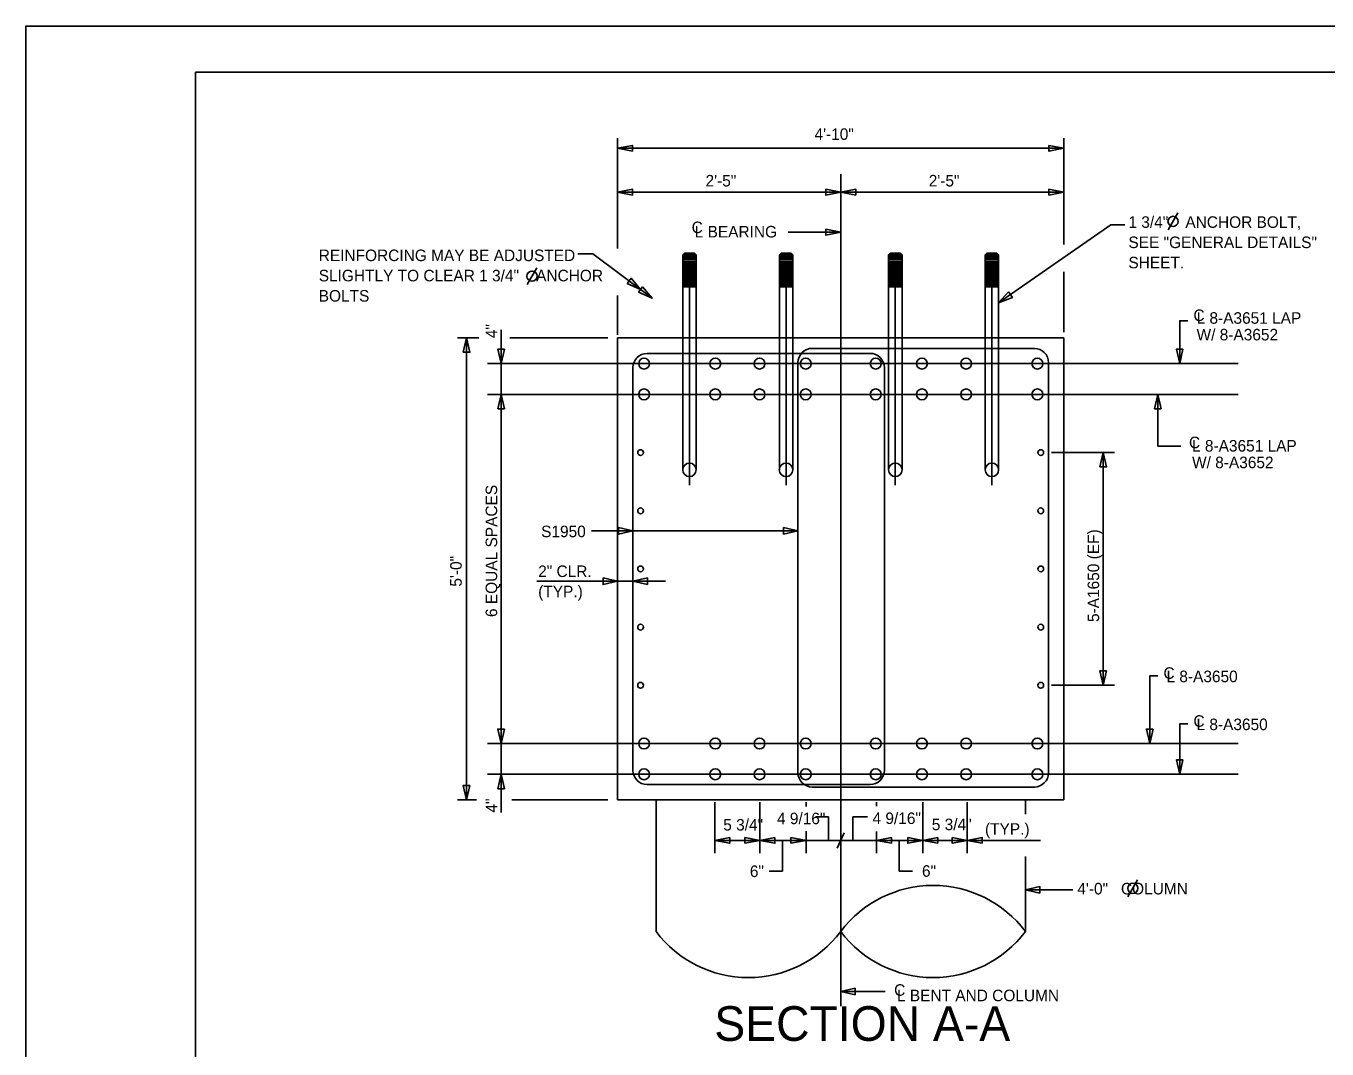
# Model space of a CAD drawing. Extents: x 1970675.2 to 1970711.3, y 796145.2 to 796167.2.
# Drawn here: x 1970675.24 to 1970689.32, y 796156.18 to 796167.25 of the extents above; entities that cross this region are included whole.
import ezdxf

# ---------------------------------------------------------------- set-up
doc = ezdxf.new("R2010")
doc.units = 0
for name, color, linetype in [('BR_AUTO DIMENSION', 7, 'Continuous'), ('BR_BORDER LINES', 7, 'Continuous'), ('BR_CENTER LINES', 7, 'Continuous'), ('BR_CONCRETE', 7, 'Continuous'), ('BR_REBAR', 7, 'Continuous'), ('BR_STRUCTURAL STEEL', 7, 'Continuous'), ('BR_TEXT', 7, 'Continuous'), ('Level 31', 7, 'Continuous')]:
    doc.layers.add(name, color=color, linetype=linetype)

msp = doc.modelspace()

# ---------------------------------------------------------------- linework, layer by layer
at = {"layer": 'BR_AUTO DIMENSION'}
for p, q in [((1970681.641, 796164.84), (1970681.641, 796166.031)), ((1970686.474, 796164.881), (1970686.474, 796166.031)), ((1970681.641, 796165.924), (1970686.474, 796165.924)), ((1970684.058, 796165.275), (1970684.058, 796165.643)), ((1970681.641, 796165.448), (1970684.058, 796165.448)), ((1970686.474, 796165.448), (1970684.058, 796165.448)), ((1970685.768, 796164.249), (1970686.981, 796165.095)), ((1970686.981, 796165.095), (1970687.135, 796165.095)), ((1970683.488, 796165.015), (1970684.058, 796165.015)), ((1970686.474, 796163.933), (1970686.474, 796164.585)), ((1970681.641, 796163.904), (1970681.641, 796164.33)), ((1970680.381, 796163.96), (1970680.381, 796158.734)), ((1970680.138, 796163.871), (1970679.908, 796163.871)), ((1970680.006, 796163.871), (1970680.006, 796158.871)), ((1970681.537, 796163.871), (1970680.475, 796163.871)), ((1970687.491, 796163.26), (1970687.491, 796162.698)), ((1970687.491, 796162.698), (1970687.742, 796162.698)), ((1970687.021, 796162.63), (1970686.339, 796162.63)), ((1970686.898, 796162.63), (1970686.898, 796160.111)), ((1970683.595, 796161.783), (1970681.361, 796161.783)), ((1970682.159, 796161.238), (1970680.767, 796161.238)), ((1970687.021, 796160.111), (1970686.339, 796160.111)), ((1970680.113, 796158.871), (1970679.908, 796158.871)), ((1970681.537, 796158.871), (1970680.496, 796158.871)), ((1970682.694, 796158.295), (1970682.694, 796158.847)), ((1970683.182, 796158.295), (1970683.182, 796158.847)), ((1970683.682, 796158.798), (1970683.682, 796158.847)), ((1970684.446, 796158.803), (1970684.446, 796158.847)), ((1970684.946, 796158.295), (1970684.946, 796158.847)), ((1970685.428, 796158.295), (1970685.428, 796158.847)), ((1970685.428, 796158.295), (1970685.428, 796158.847)), ((1970683.784, 796158.687), (1970683.926, 796158.687)), ((1970683.926, 796158.433), (1970683.926, 796158.687)), ((1970684.19, 796158.687), (1970684.347, 796158.687)), ((1970684.19, 796158.433), (1970684.19, 796158.687)), ((1970685.428, 796158.433), (1970682.694, 796158.433)), ((1970683.426, 796158.433), (1970683.426, 796158.1)), ((1970683.682, 796158.295), (1970683.682, 796158.532)), ((1970684.021, 796158.35), (1970684.095, 796158.515)), ((1970684.446, 796158.295), (1970684.446, 796158.528)), ((1970684.692, 796158.433), (1970684.692, 796158.1)), ((1970686.22, 796158.433), (1970685.428, 796158.433)), ((1970683.426, 796158.1), (1970683.282, 796158.1)), ((1970684.692, 796158.1), (1970684.836, 796158.1)), ((1970686.058, 796157.896), (1970686.57, 796157.896)), ((1970684.058, 796156.797), (1970684.54, 796156.797))]:
    msp.add_line(p, q, dxfattribs=at)
for points in [[(1970681.804, 796165.892), (1970681.641, 796165.924), (1970681.804, 796165.955)], [(1970686.312, 796165.955), (1970686.474, 796165.924), (1970686.312, 796165.892)], [(1970681.804, 796165.417), (1970681.641, 796165.448), (1970681.804, 796165.479)], [(1970683.895, 796165.479), (1970684.058, 796165.448), (1970683.895, 796165.417)], [(1970684.22, 796165.417), (1970684.058, 796165.448), (1970684.22, 796165.479)], [(1970686.312, 796165.479), (1970686.474, 796165.448), (1970686.312, 796165.417)], [(1970683.895, 796165.047), (1970684.058, 796165.015), (1970683.895, 796164.984)], [(1970681.745, 796164.459), (1970681.891, 796164.394), (1970681.788, 796164.516)], [(1970681.87, 796164.365), (1970682.016, 796164.301), (1970681.913, 796164.423)], [(1970685.875, 796164.368), (1970685.768, 796164.249), (1970685.917, 796164.309)], [(1970679.97, 796163.715), (1970680.006, 796163.871), (1970680.042, 796163.715)], [(1970680.417, 796163.749), (1970680.381, 796163.593), (1970680.345, 796163.749)], [(1970687.764, 796163.749), (1970687.728, 796163.593), (1970687.692, 796163.749)], [(1970680.345, 796163.104), (1970680.381, 796163.26), (1970680.417, 796163.104)], [(1970687.527, 796163.104), (1970687.491, 796163.26), (1970687.455, 796163.104)], [(1970686.862, 796162.474), (1970686.898, 796162.63), (1970686.934, 796162.474)], [(1970681.652, 796161.819), (1970681.808, 796161.783), (1970681.652, 796161.747)], [(1970683.439, 796161.819), (1970683.595, 796161.783), (1970683.439, 796161.747)], [(1970681.485, 796161.274), (1970681.641, 796161.238), (1970681.485, 796161.202)], [(1970681.964, 796161.202), (1970681.808, 796161.238), (1970681.964, 796161.274)], [(1970686.934, 796160.267), (1970686.898, 796160.111), (1970686.862, 796160.267)], [(1970680.417, 796159.637), (1970680.381, 796159.481), (1970680.345, 796159.637)], [(1970687.44, 796159.637), (1970687.404, 796159.481), (1970687.368, 796159.637)], [(1970687.764, 796159.304), (1970687.728, 796159.148), (1970687.692, 796159.304)], [(1970680.345, 796158.992), (1970680.381, 796159.148), (1970680.417, 796158.992)], [(1970680.042, 796159.027), (1970680.006, 796158.871), (1970679.97, 796159.027)], [(1970682.857, 796158.464), (1970682.694, 796158.433), (1970682.857, 796158.402)], [(1970683.02, 796158.402), (1970683.182, 796158.433), (1970683.02, 796158.464)], [(1970683.345, 796158.464), (1970683.182, 796158.433), (1970683.345, 796158.402)], [(1970683.519, 796158.402), (1970683.682, 796158.433), (1970683.519, 796158.464)], [(1970684.609, 796158.402), (1970684.446, 796158.433), (1970684.609, 796158.464)], [(1970684.784, 796158.464), (1970684.946, 796158.433), (1970684.784, 796158.402)], [(1970685.109, 796158.402), (1970684.946, 796158.433), (1970685.109, 796158.464)], [(1970685.266, 796158.464), (1970685.428, 796158.433), (1970685.266, 796158.402)], [(1970685.591, 796158.402), (1970685.428, 796158.433), (1970685.591, 796158.464)], [(1970686.214, 796157.86), (1970686.058, 796157.896), (1970686.214, 796157.932)], [(1970684.214, 796156.761), (1970684.058, 796156.797), (1970684.214, 796156.833)]]:
    msp.add_lwpolyline(points, close=True, dxfattribs=at)
for points in [[(1970682.016, 796164.301), (1970681.375, 796164.78), (1970681.21, 796164.78)], [(1970687.728, 796163.593), (1970687.728, 796164.056), (1970687.816, 796164.056)], [(1970687.404, 796159.481), (1970687.404, 796160.213), (1970687.491, 796160.213)], [(1970687.728, 796159.148), (1970687.728, 796159.694), (1970687.816, 796159.694)]]:
    msp.add_lwpolyline(points, dxfattribs=at)
at = {"layer": 'BR_BORDER LINES'}
for p in [(1970710.736, 796166.746), (1970677.07, 796145.746)]:
    msp.add_line(p, (1970677.07, 796166.746), dxfattribs=at)
at = {"layer": 'BR_CENTER LINES'}
for p, q in [((1970684.058, 796165.553), (1970684.058, 796156.638)), ((1970682.42, 796162.277), (1970682.42, 796164.576)), ((1970683.466, 796162.277), (1970683.466, 796164.576)), ((1970684.649, 796162.277), (1970684.649, 796164.576)), ((1970685.695, 796162.277), (1970685.695, 796164.576)), ((1970680.233, 796163.593), (1970688.361, 796163.593)), ((1970680.233, 796163.26), (1970688.361, 796163.26)), ((1970680.233, 796159.481), (1970688.361, 796159.481)), ((1970680.233, 796159.148), (1970688.361, 796159.148))]:
    msp.add_line(p, q, dxfattribs=at)
at = {"layer": 'BR_CONCRETE'}
for p, q in [((1970681.641, 796163.871), (1970681.641, 796159.037)), ((1970681.641, 796158.871), (1970681.641, 796163.871)), ((1970686.474, 796163.871), (1970681.641, 796163.871)), ((1970686.474, 796163.871), (1970686.474, 796158.871)), ((1970681.641, 796158.871), (1970686.474, 796158.871)), ((1970682.058, 796158.871), (1970682.058, 796158.568)), ((1970686.058, 796158.871), (1970686.058, 796158.715)), ((1970682.058, 796158.568), (1970682.058, 796157.446)), ((1970686.058, 796158.259), (1970686.058, 796157.446))]:
    msp.add_line(p, q, dxfattribs=at)
for centre, start, end in [((1970685.058, 796156.693), 37.0023, 142.9977), ((1970683.058, 796158.2), 217.0023, 322.9977), ((1970685.058, 796158.2), 217.0023, 322.9977)]:
    msp.add_arc(centre, 1.252, start, end, dxfattribs=at)
at = {"layer": 'BR_REBAR'}
for p, q in [((1970681.962, 796163.704), (1970684.375, 796163.704)), ((1970686.154, 796163.758), (1970683.751, 796163.758)), ((1970681.808, 796163.55), (1970681.808, 796159.191)), ((1970683.595, 796163.602), (1970683.595, 796159.166)), ((1970684.531, 796163.548), (1970684.531, 796159.193)), ((1970686.308, 796163.605), (1970686.308, 796159.164)), ((1970681.961, 796159.037), (1970684.375, 796159.037)), ((1970686.154, 796159.01), (1970683.751, 796159.01))]:
    msp.add_line(p, q, dxfattribs=at)
for centre, radius in [((1970681.929, 796163.593), 0.0588), ((1970682.7, 796163.593), 0.0588), ((1970683.179, 796163.593), 0.0588), ((1970683.679, 796163.593), 0.0588), ((1970684.437, 796163.593), 0.0588), ((1970684.937, 796163.593), 0.0588), ((1970685.416, 796163.593), 0.0588), ((1970686.187, 796163.593), 0.0588), ((1970681.929, 796163.26), 0.0588), ((1970682.7, 796163.26), 0.0588), ((1970683.179, 796163.26), 0.0588), ((1970683.679, 796163.26), 0.0588), ((1970684.437, 796163.26), 0.0588), ((1970684.937, 796163.26), 0.0588), ((1970685.416, 796163.26), 0.0588), ((1970686.187, 796163.26), 0.0588), ((1970681.891, 796162.63), 0.0313), ((1970686.224, 796162.63), 0.0313), ((1970681.891, 796162), 0.0313), ((1970686.224, 796162), 0.0313), ((1970681.891, 796161.371), 0.0313), ((1970686.224, 796161.371), 0.0313), ((1970681.891, 796160.741), 0.0313), ((1970686.224, 796160.741), 0.0313), ((1970681.891, 796160.111), 0.0313), ((1970686.224, 796160.111), 0.0313), ((1970681.929, 796159.481), 0.0588), ((1970682.7, 796159.481), 0.0588), ((1970683.179, 796159.481), 0.0588), ((1970683.679, 796159.481), 0.0588), ((1970684.437, 796159.481), 0.0588), ((1970684.937, 796159.481), 0.0588), ((1970685.416, 796159.481), 0.0588), ((1970686.187, 796159.481), 0.0588), ((1970681.929, 796159.148), 0.0588), ((1970682.7, 796159.148), 0.0588), ((1970683.179, 796159.148), 0.0588), ((1970683.679, 796159.148), 0.0588), ((1970684.437, 796159.148), 0.0588), ((1970684.937, 796159.148), 0.0588), ((1970685.416, 796159.148), 0.0588), ((1970686.187, 796159.148), 0.0588)]:
    msp.add_circle(centre, radius, dxfattribs=at)
for centre, start, end in [((1970681.964, 796163.548), 91.025, 178.975), ((1970683.751, 796163.602), 90, 180), ((1970684.375, 796163.548), 0, 90), ((1970686.152, 796163.602), 1.025, 88.975), ((1970681.964, 796159.193), 181.025, 268.975), ((1970683.751, 796159.166), 180, 270), ((1970684.375, 796159.193), 270, 0), ((1970686.152, 796159.166), 271.025, 358.975)]:
    msp.add_arc(centre, 0.156, start, end, dxfattribs=at)
at = {"layer": 'BR_STRUCTURAL STEEL'}
for p, q in [((1970682.347, 796164.769), (1970682.366, 796164.787)), ((1970682.347, 796164.769), (1970682.493, 796164.769)), ((1970682.347, 796164.769), (1970682.347, 796163.871)), ((1970682.347, 796164.751), (1970682.493, 796164.751)), ((1970682.366, 796164.787), (1970682.475, 796164.787)), ((1970682.475, 796164.787), (1970682.493, 796164.769)), ((1970682.493, 796164.769), (1970682.493, 796163.871)), ((1970683.412, 796164.787), (1970683.394, 796164.769)), ((1970683.539, 796164.769), (1970683.394, 796164.769)), ((1970683.394, 796164.769), (1970683.394, 796163.871)), ((1970683.539, 796164.751), (1970683.394, 796164.751)), ((1970683.521, 796164.787), (1970683.412, 796164.787)), ((1970683.539, 796164.769), (1970683.521, 796164.787)), ((1970683.539, 796164.769), (1970683.539, 796163.871)), ((1970684.594, 796164.787), (1970684.576, 796164.769)), ((1970684.722, 796164.769), (1970684.576, 796164.769)), ((1970684.576, 796164.769), (1970684.576, 796163.871)), ((1970684.722, 796164.751), (1970684.576, 796164.751)), ((1970684.704, 796164.787), (1970684.594, 796164.787)), ((1970684.722, 796164.769), (1970684.704, 796164.787)), ((1970684.722, 796164.769), (1970684.722, 796163.871)), ((1970685.641, 796164.787), (1970685.622, 796164.769)), ((1970685.768, 796164.769), (1970685.622, 796164.769)), ((1970685.622, 796164.769), (1970685.622, 796163.871)), ((1970685.768, 796164.751), (1970685.622, 796164.751)), ((1970685.75, 796164.787), (1970685.641, 796164.787)), ((1970685.768, 796164.769), (1970685.75, 796164.787)), ((1970685.768, 796164.769), (1970685.768, 796163.871)), ((1970682.347, 796164.733), (1970682.493, 796164.733)), ((1970682.347, 796164.715), (1970682.493, 796164.715)), ((1970682.347, 796164.696), (1970682.493, 796164.696)), ((1970682.347, 796164.678), (1970682.493, 796164.678)), ((1970682.347, 796164.66), (1970682.493, 796164.66)), ((1970682.347, 796164.642), (1970682.493, 796164.642)), ((1970682.347, 796164.623), (1970682.493, 796164.623)), ((1970682.347, 796164.605), (1970682.493, 796164.605)), ((1970683.539, 796164.733), (1970683.394, 796164.733)), ((1970683.539, 796164.715), (1970683.394, 796164.715)), ((1970683.539, 796164.696), (1970683.394, 796164.696)), ((1970683.539, 796164.678), (1970683.394, 796164.678)), ((1970683.539, 796164.66), (1970683.394, 796164.66)), ((1970683.539, 796164.642), (1970683.394, 796164.642)), ((1970683.539, 796164.623), (1970683.394, 796164.623)), ((1970683.539, 796164.605), (1970683.394, 796164.605)), ((1970684.722, 796164.733), (1970684.576, 796164.733)), ((1970684.722, 796164.715), (1970684.576, 796164.715)), ((1970684.722, 796164.696), (1970684.576, 796164.696)), ((1970684.722, 796164.678), (1970684.576, 796164.678)), ((1970684.722, 796164.66), (1970684.576, 796164.66)), ((1970684.722, 796164.642), (1970684.576, 796164.642)), ((1970684.722, 796164.623), (1970684.576, 796164.623)), ((1970684.722, 796164.605), (1970684.576, 796164.605)), ((1970685.768, 796164.733), (1970685.622, 796164.733)), ((1970685.768, 796164.715), (1970685.622, 796164.715)), ((1970685.768, 796164.696), (1970685.622, 796164.696)), ((1970685.768, 796164.678), (1970685.622, 796164.678)), ((1970685.768, 796164.66), (1970685.622, 796164.66)), ((1970685.768, 796164.642), (1970685.622, 796164.642)), ((1970685.768, 796164.623), (1970685.622, 796164.623)), ((1970685.768, 796164.605), (1970685.622, 796164.605)), ((1970682.347, 796164.587), (1970682.493, 796164.587)), ((1970682.347, 796164.569), (1970682.493, 796164.569)), ((1970682.347, 796164.551), (1970682.493, 796164.551)), ((1970682.347, 796164.532), (1970682.493, 796164.532)), ((1970682.347, 796164.514), (1970682.493, 796164.514)), ((1970682.347, 796164.496), (1970682.493, 796164.496)), ((1970682.347, 796164.478), (1970682.493, 796164.478)), ((1970683.539, 796164.587), (1970683.394, 796164.587)), ((1970683.539, 796164.569), (1970683.394, 796164.569)), ((1970683.539, 796164.551), (1970683.394, 796164.551)), ((1970683.539, 796164.532), (1970683.394, 796164.532)), ((1970683.539, 796164.514), (1970683.394, 796164.514)), ((1970683.539, 796164.496), (1970683.394, 796164.496)), ((1970683.539, 796164.478), (1970683.394, 796164.478)), ((1970684.722, 796164.587), (1970684.576, 796164.587)), ((1970684.722, 796164.569), (1970684.576, 796164.569)), ((1970684.722, 796164.551), (1970684.576, 796164.551)), ((1970684.722, 796164.532), (1970684.576, 796164.532)), ((1970684.722, 796164.514), (1970684.576, 796164.514)), ((1970684.722, 796164.496), (1970684.576, 796164.496)), ((1970684.722, 796164.478), (1970684.576, 796164.478)), ((1970685.768, 796164.587), (1970685.622, 796164.587)), ((1970685.768, 796164.569), (1970685.622, 796164.569)), ((1970685.768, 796164.551), (1970685.622, 796164.551)), ((1970685.768, 796164.532), (1970685.622, 796164.532)), ((1970685.768, 796164.514), (1970685.622, 796164.514)), ((1970685.768, 796164.496), (1970685.622, 796164.496)), ((1970685.768, 796164.478), (1970685.622, 796164.478)), ((1970682.347, 796164.459), (1970682.493, 796164.459)), ((1970682.347, 796164.441), (1970682.493, 796164.441)), ((1970682.347, 796164.423), (1970682.493, 796164.423)), ((1970683.539, 796164.459), (1970683.394, 796164.459)), ((1970683.539, 796164.441), (1970683.394, 796164.441)), ((1970683.539, 796164.423), (1970683.394, 796164.423)), ((1970684.722, 796164.459), (1970684.576, 796164.459)), ((1970684.722, 796164.441), (1970684.576, 796164.441)), ((1970684.722, 796164.423), (1970684.576, 796164.423)), ((1970685.768, 796164.459), (1970685.622, 796164.459)), ((1970685.768, 796164.441), (1970685.622, 796164.441)), ((1970685.768, 796164.423), (1970685.622, 796164.423)), ((1970682.347, 796163.871), (1970682.347, 796162.446)), ((1970682.493, 796163.871), (1970682.493, 796162.443)), ((1970683.394, 796163.871), (1970683.394, 796162.443)), ((1970683.539, 796163.871), (1970683.539, 796162.446)), ((1970684.576, 796163.871), (1970684.576, 796162.443)), ((1970684.722, 796163.871), (1970684.722, 796162.446)), ((1970685.622, 796163.871), (1970685.622, 796162.443)), ((1970685.768, 796163.871), (1970685.768, 796162.446))]:
    msp.add_line(p, q, dxfattribs=at)
for centre in [(1970682.42, 796162.443), (1970683.466, 796162.443), (1970684.649, 796162.443), (1970685.695, 796162.443)]:
    msp.add_circle(centre, 0.0729, dxfattribs=at)
at = {"layer": 'BR_TEXT'}
for p, q in [((1970687.603, 796165.041), (1970687.708, 796165.223)), ((1970680.662, 796164.449), (1970680.767, 796164.63)), ((1970686.898, 796160.111), (1970686.898, 796160.259)), ((1970680.006, 796158.871), (1970680.006, 796159.018)), ((1970687.167, 796157.823), (1970687.272, 796158.005))]:
    msp.add_line(p, q, dxfattribs=at)
for centre in [(1970687.656, 796165.132), (1970680.715, 796164.54), (1970687.22, 796157.914)]:
    msp.add_circle(centre, 0.055, dxfattribs=at)
at = {"layer": 'Level 31'}
msp.add_lwpolyline([(1970675.236, 796145.246), (1970711.236, 796145.246), (1970711.236, 796167.246), (1970675.236, 796167.246)], close=True, dxfattribs=at)

# ---------------------------------------------------------------- texts
at = {"layer": 'BR_AUTO DIMENSION'}
for s, p in [('4\'-10"', (1970683.774, 796166.014)), ('2\'-5"', (1970682.594, 796165.51)), ('2\'-5"', (1970685.011, 796165.51))]:
    msp.add_text(s, height=0.125, dxfattribs=at).set_placement(p)
at = {"layer": 'BR_TEXT'}
for s, rotation, p in [('1 3/4"    ANCHOR BOLT, ', 360, (1970687.173, 796165.062)), ('SEE "GENERAL DETAILS"', 360, (1970687.173, 796164.843)), ('REINFORCING MAY BE ADJUSTED', 360, (1970678.406, 796164.702)), ('SHEET.', 360, (1970687.173, 796164.624)), ('SLIGHTLY TO CLEAR 1 3/4"    ANCHOR', 360, (1970678.406, 796164.483)), ('BOLTS', 360, (1970678.406, 796164.264)), ('4"', 90, (1970680.338, 796163.868)), ('C', 360, (1970687.829, 796162.677)), ('L 8-A3651 LAP', 360, (1970687.862, 796162.641)), ('W/ 8-A3652', 360, (1970687.862, 796162.461)), ('6 EQUAL SPACES', 90, (1970680.338, 796160.85)), ('5-A1650 (EF)', 90, (1970686.856, 796160.796)), ('5\'-0"', 90, (1970679.954, 796161.179)), ('C', 360, (1970687.553, 796160.181)), ('L 8-A3650', 360, (1970687.585, 796160.145)), ('C', 360, (1970687.877, 796159.662)), ('L 8-A3650', 360, (1970687.91, 796159.626)), ('4"', 90, (1970680.338, 796158.734)), ('5 3/4"', 360, (1970682.786, 796158.539)), ('5 3/4"', 360, (1970685.044, 796158.543)), ('(TYP.)', 360, (1970685.62, 796158.494)), ('6"', 360, (1970683.074, 796158.036)), ('6"', 360, (1970684.938, 796158.039)), ('4\'-0"   COLUMN', 360, (1970686.62, 796157.848)), ('C', 360, (1970684.636, 796156.751)), ('L BENT AND COLUMN', 360, (1970684.667, 796156.692))]:
    msp.add_text(s, height=0.125, rotation=rotation, dxfattribs=at).set_placement(p)
for s, height, p in [('C', 0.125, (1970682.444, 796165.005)), ('L BEARING', 0.125, (1970682.477, 796164.958)), ('C', 0.125, (1970687.877, 796164.053)), ('L 8-A3651 LAP', 0.125, (1970687.911, 796164.024)), ('W/ 8-A3652', 0.125, (1970687.911, 796163.844)), ('S1950', 0.125, (1970680.814, 796161.714)), ('2" CLR.', 0.125, (1970680.782, 796161.283)), ('(TYP.)', 0.125, (1970680.782, 796161.064)), ('4 9/16"', 0.125, (1970683.368, 796158.608)), ('4 9/16"', 0.125, (1970684.402, 796158.61)), ('SECTION A-A', 0.375, (1970682.689, 796156.263))]:
    msp.add_text(s, height=height, dxfattribs=at).set_placement(p)

doc.saveas('drawing.dxf')
